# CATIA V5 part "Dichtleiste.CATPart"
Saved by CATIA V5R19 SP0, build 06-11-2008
Part number: Part1
Bounding box of the stored display mesh (mm): x 0 to 30, y -1 to 1, z -3.5 to 4.5
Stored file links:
  H:\Bachelorarbeit_Hahn\Neue Vereinfachung\Dichtleiste.CATPart
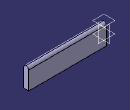
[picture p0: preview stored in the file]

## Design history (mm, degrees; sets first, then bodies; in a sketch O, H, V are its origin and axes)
Body1 (main body)
  Sketch1 on yz-plane, origin (0, 0, 0), H (0, 1, 0), V (0, 0, 1)
    line L1 (1, 3.5) -> (1, -3.5)
    line L2 (1, -3.5) -> (-1, -3.5)
    line L3 (-1, -3.5) -> (-1, 3.5)
    point P5 (0, 4.5)
    arc A1 centre (0, 3.5) radius 1 from (1, 3.5) to (0, 4.5) ccw
    point P6 (0, 3.5)
    arc A2 centre (0, 3.5) radius 1 from (0, 4.5) to (-1, 3.5) ccw
    distance L1 L3 = 2
    vertical: L1 V, L3 V
    horizontal: L2 H
    equidistance: L1 L3 O
    coincidence: P5 V, P6 V
    tangency: A1 L1, A2 L1
  Pad1: profile Sketch1, direction (1, 0, 0), length 30
  Plane1: type Offset, Offset 4.5, RefPlane xy-plane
